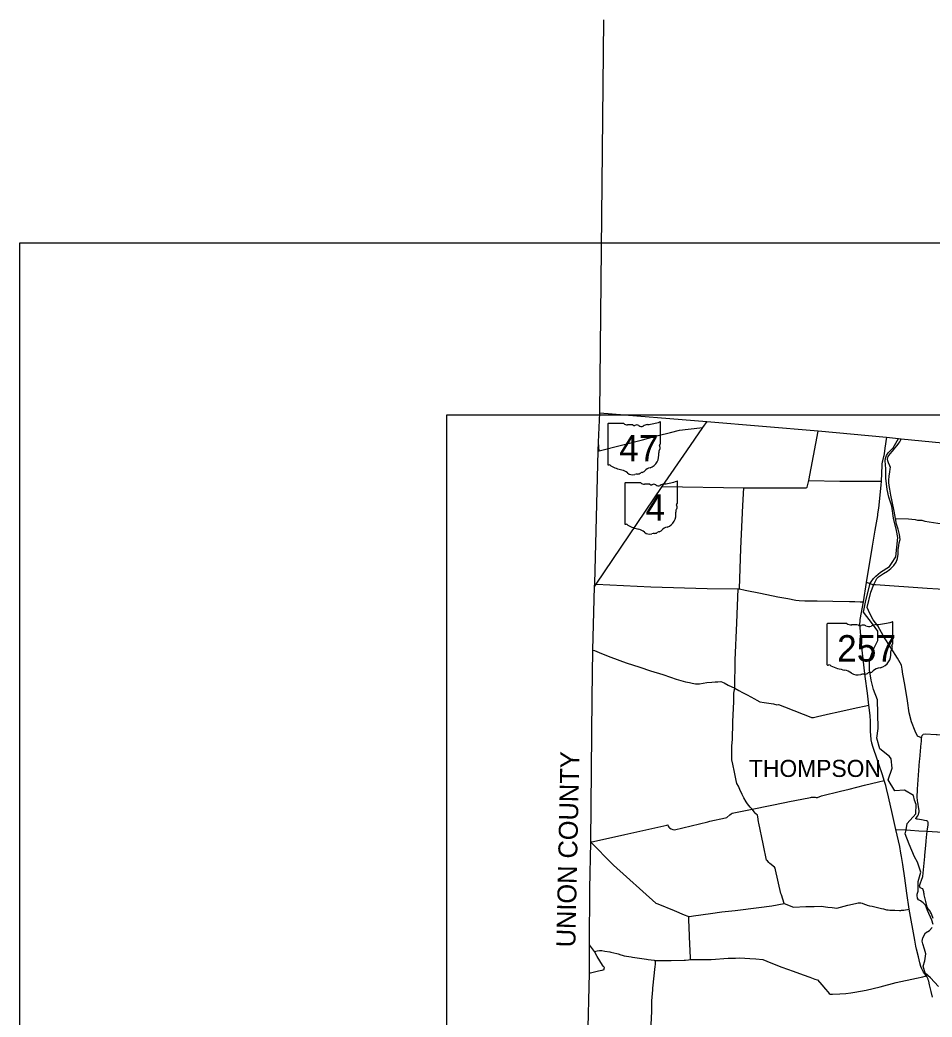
# Model space of a CAD drawing. Extents: x 1729596 to 1925846, y 659247 to 911751.
# Drawn here: x 1729596 to 1777664, y 859172 to 911751 of the extents above; entities that cross this region are included whole.
import ezdxf

# ---------------------------------------------------------------- set-up
doc = ezdxf.new("R2010")
doc.units = 0
for name, color, linetype in [('GM_X_Adjacent_County', 7, 'Continuous'), ('GM_X_Adjacent_County_Text', 7, 'Continuous'), ('GM_X_County', 7, 'Continuous'), ('GM_X_County_Road', 7, 'Continuous'), ('GM_X_State_Route', 7, 'Continuous'), ('GM_X_State_Shield', 7, 'Continuous'), ('GM_X_Township', 7, 'Continuous'), ('GM_X_Township_Road', 7, 'Continuous'), ('GM_X_Township_Text', 7, 'Continuous'), ('SC_Scratch1', 7, 'Continuous'), ('SH_Data', 7, 'Continuous')]:
    doc.layers.add(name, color=color, linetype=linetype)

msp = doc.modelspace()

# ---------------------------------------------------------------- linework, layer by layer
at = {"layer": 'GM_X_Adjacent_County'}
msp.add_line((1760161, 891042), (1760364, 911751), dxfattribs=at)
at = {"layer": 'GM_X_County'}
msp.add_lwpolyline([(1759518, 857896), (1759604, 861482), (1759615, 862978), (1759631, 865937), (1759690, 868390), (1759745, 876009), (1759795, 878524), (1759881, 881868), (1759886, 882027), (1760071, 889009), (1760084, 889480), (1760161, 891042), (1765804, 890577), (1771666, 890080), (1775269, 889747), (1775894, 889674), (1776032, 889658), (1778209, 889456)], dxfattribs=at)
at = {"layer": 'GM_X_County_Road'}
for points in [[(1759969, 881997), (1762841, 881858), (1765814, 881778), (1767451, 881759), (1767471, 881758), (1767516, 881753), (1767813, 881684), (1768617, 881522), (1769536, 881337), (1770062, 881247), (1770477, 881159), (1770666, 881130), (1770953, 881125), (1771606, 881121), (1772443, 881104), (1773313, 881088), (1773587, 881081), (1773877, 881076), (1773962, 881074), (1774048, 881064)], [(1774211, 882090), (1774252, 882089), (1774404, 882033)], [(1774404, 882033), (1774406, 882032), (1774523, 881989), (1774565, 881978), (1774598, 881976), (1774681, 881977), (1777408, 881796), (1778560, 881723), (1779427, 881668), (1779984, 881633), (1780423, 881605), (1780749, 881582)], [(1759795, 878524), (1759874, 878494), (1760252, 878350), (1760733, 878141), (1761552, 877854), (1762256, 877623), (1762819, 877435), (1763473, 877228), (1763875, 877098), (1764180, 876995), (1764428, 876912), (1764673, 876852), (1764882, 876805), (1765024, 876776), (1765203, 876738), (1765411, 876747), (1765804, 876809), (1766052, 876831), (1766236, 876847), (1766368, 876855), (1766526, 876867), (1766703, 876800), (1766927, 876678), (1767271, 876519)], [(1767271, 876519), (1767477, 876397), (1767681, 876278), (1767921, 876172), (1768111, 876051), (1768305, 875950), (1768436, 875882), (1768593, 875793), (1768820, 875758), (1769062, 875716), (1769301, 875685), (1769490, 875642), (1769580, 875657), (1769884, 875528), (1770879, 875150), (1771192, 875019), (1771304, 874972), (1771344, 874966), (1771384, 874967), (1771424, 874974), (1771622, 875018), (1772316, 875174), (1772655, 875249), (1773509, 875437), (1774333, 875620)], [(1775757, 869068), (1776296, 869048), (1776328, 869045)], [(1776328, 869045), (1776526, 869023), (1776962, 868999), (1777415, 868976), (1778218, 868930)]]:
    msp.add_lwpolyline(points, dxfattribs=at)
at = {"layer": 'GM_X_State_Route'}
for points in [[(1759881, 881868), (1759956, 881980), (1759969, 881997), (1763443, 887141), (1764744, 889038), (1765591, 890255), (1765808, 890573)], [(1760071, 889009), (1760118, 889022), (1762397, 889618), (1763225, 889831), (1763889, 890004), (1764355, 890118), (1764820, 890175), (1765591, 890255)], [(1777685, 860217), (1777620, 860525), (1777532, 860880), (1777486, 861060), (1777476, 861098), (1777464, 861135), (1777451, 861171), (1777436, 861207), (1777419, 861242), (1777383, 861311), (1777355, 861355), (1777221, 861539), (1777176, 861609), (1777119, 861721), (1777075, 861838), (1777027, 862032), (1776950, 862347), (1776840, 862758), (1776807, 862917), (1776749, 863221), (1776467, 864856), (1776332, 865707), (1776223, 866494), (1776116, 867210), (1776059, 867642), (1776027, 867820), (1775960, 868164), (1775757, 869068), (1775581, 869857), (1775376, 870780), (1775268, 871225), (1775225, 871389), (1775149, 871651), (1775057, 871948), (1774882, 872459), (1774774, 872777), (1774561, 873391), (1774496, 873614), (1774491, 873632), (1774460, 873783), (1774453, 873834), (1774417, 874231), (1774413, 874823), (1774404, 875011), (1774397, 875080), (1774333, 875620), (1774258, 876258), (1774139, 877129), (1774064, 877743), (1773968, 878674), (1773866, 879905), (1773869, 880029), (1773882, 880140), (1774048, 881064), (1774211, 882090), (1774530, 884003), (1774667, 884846), (1774801, 885624), (1774814, 885707), (1774851, 886003), (1774976, 887219), (1774992, 887423), (1775028, 888248), (1775030, 888289), (1775035, 888331), (1775040, 888372), (1775048, 888413), (1775057, 888454), (1775067, 888494), (1775128, 888732), (1775139, 888776), (1775154, 888865), (1775187, 889163), (1775276, 889757)]]:
    msp.add_lwpolyline(points, dxfattribs=at)
at = {"layer": 'GM_X_State_Shield'}
for p, q in [((1760571, 890435), (1760571, 888322)), ((1760571, 890435), (1760571, 888322)), ((1761414, 890471), (1760599, 890471)), ((1761414, 890471), (1760599, 890471)), ((1763356, 889418), (1763356, 890524)), ((1763356, 889418), (1763356, 890524)), ((1763355, 889418), (1763356, 889418)), ((1763355, 889418), (1763356, 889418)), ((1761469, 887306), (1761469, 885193)), ((1761469, 887306), (1761469, 885193)), ((1762312, 887343), (1761496, 887343)), ((1762312, 887343), (1761496, 887343)), ((1764253, 886290), (1764253, 887395)), ((1764253, 886290), (1764253, 887395)), ((1764253, 886290), (1764253, 886290)), ((1764253, 886290), (1764253, 886290)), ((1772124, 879884), (1772124, 877770)), ((1772124, 879884), (1772124, 877770)), ((1773178, 879920), (1772159, 879920)), ((1773178, 879920), (1772159, 879920)), ((1775605, 878867), (1775605, 879972)), ((1775605, 878867), (1775605, 879972)), ((1775604, 878867), (1775605, 878867)), ((1775604, 878867), (1775605, 878867))]:
    msp.add_line(p, q, dxfattribs=at)
for centre, radius, start, end in [((1760603, 890439), 32.3, 98.1301, 188.1301), ((1760603, 890439), 32.3, 98.1301, 188.1301), ((1761608, 890717), 313, 231.6195, 271.1119), ((1761608, 890717), 313, 231.6195, 271.1119), ((1761712, 889285), 1123, 80.4867, 94.9883), ((1761712, 889285), 1123, 80.4867, 94.9883), ((1761967, 890450), 90.3, 219.7921, 297.1024), ((1761967, 890450), 90.3, 219.7921, 297.1024), ((1762100, 890206), 188, 54.4667, 119.1411), ((1762100, 890206), 188, 54.4667, 119.1411), ((1762342, 890541), 226, 233.8562, 294.8282), ((1762342, 890541), 226, 233.8562, 294.8282), ((1762741, 889826), 594, 97.3462, 120.7689), ((1762741, 889826), 594, 97.3462, 120.7689), ((1762364, 893352), 2953, 275.8445, 288.9065), ((1762364, 893352), 2953, 275.8445, 288.9065), ((1763325, 890528), 31, 351.8621, 97.738), ((1763325, 890528), 31, 351.8621, 97.738), ((1763349, 889337), 48, 107.944, 210.337), ((1763349, 889337), 48, 107.944, 210.337), ((1763043, 889197), 288, 340.033, 23.6496), ((1763043, 889197), 288, 340.033, 23.6496), ((1763323, 889414), 33.2, 289.6038, 7.7341), ((1763323, 889414), 33.2, 289.6038, 7.7341), ((1762529, 888815), 739, 292.3089, 8.9858), ((1762529, 888815), 739, 292.3089, 8.9858), ((1763467, 888955), 210, 136.8065, 186.9296), ((1763467, 888955), 210, 136.8065, 186.9296), ((1760604, 888317), 32.5, 171.9584, 258.3066), ((1760604, 888317), 32.5, 171.9584, 258.3066), ((1760609, 888533), 248, 267.339, 280.6039), ((1760609, 888533), 248, 267.339, 280.6039), ((1760659, 888200), 89.5, 29.7484, 93.2717), ((1760659, 888200), 89.5, 29.7484, 93.2717), ((1761790, 890098), 2132, 240.4129, 257.1985), ((1761790, 890098), 2132, 240.4129, 257.1985), ((1762841, 887728), 404, 94.4031, 142.5768), ((1762841, 887728), 404, 94.4031, 142.5768), ((1761154, 887372), 667, 47.1842, 75.836), ((1761154, 887372), 667, 47.1842, 75.836), ((1761876, 888189), 423, 230.7004, 286.2918), ((1761876, 888189), 423, 230.7004, 286.2918), ((1762120, 887459), 348, 85.6951, 111.2099), ((1762120, 887459), 348, 85.6951, 111.2099), ((1762151, 888031), 226, 268.777, 315.5493), ((1762151, 888031), 226, 268.777, 315.5493), ((1762355, 887826), 63.5, 65.7517, 132.6484), ((1762355, 887826), 63.5, 65.7517, 132.6484), ((1762328, 888117), 239, 282.8732, 323.2771), ((1762328, 888117), 239, 282.8732, 323.2771), ((1761501, 887311), 32.3, 98.1301, 188.1301), ((1761501, 887311), 32.3, 98.1301, 188.1301), ((1762506, 887588), 313, 231.6195, 271.1119), ((1762506, 887588), 313, 231.6195, 271.1119), ((1762610, 886156), 1123, 80.4867, 94.9883), ((1762610, 886156), 1123, 80.4867, 94.9883), ((1762865, 887322), 90.3, 219.7921, 297.1024), ((1762865, 887322), 90.3, 219.7921, 297.1024), ((1762997, 887078), 188, 54.4667, 119.1411), ((1762997, 887078), 188, 54.4667, 119.1411), ((1763239, 887413), 226, 233.8562, 294.8282), ((1763239, 887413), 226, 233.8562, 294.8282), ((1763638, 886697), 594, 97.3462, 120.7689), ((1763638, 886697), 594, 97.3462, 120.7689), ((1763261, 890224), 2953, 275.8445, 288.9065), ((1763261, 890224), 2953, 275.8445, 288.9065), ((1764222, 887400), 31, 351.8621, 97.738), ((1764222, 887400), 31, 351.8621, 97.738), ((1764364, 885827), 210, 136.8065, 186.9296), ((1764364, 885827), 210, 136.8065, 186.9296), ((1764246, 886209), 48, 107.944, 210.337), ((1764246, 886209), 48, 107.944, 210.337), ((1763941, 886069), 288, 340.033, 23.6496), ((1763941, 886069), 288, 340.033, 23.6496), ((1764220, 886285), 33.2, 289.6038, 7.7341), ((1764220, 886285), 33.2, 289.6038, 7.7341), ((1763427, 885686), 739, 292.3089, 8.9858), ((1763427, 885686), 739, 292.3089, 8.9858), ((1761501, 885189), 32.5, 171.9584, 258.3066), ((1761501, 885189), 32.5, 171.9584, 258.3066), ((1761506, 885405), 248, 267.339, 280.6039), ((1761506, 885405), 248, 267.339, 280.6039), ((1761557, 885071), 89.5, 29.7484, 93.2717), ((1761557, 885071), 89.5, 29.7484, 93.2717), ((1762687, 886970), 2132, 240.4129, 257.1985), ((1762687, 886970), 2132, 240.4129, 257.1985), ((1763738, 884600), 404, 94.4031, 142.5768), ((1763738, 884600), 404, 94.4031, 142.5768), ((1762052, 884244), 667, 47.1842, 75.836), ((1762052, 884244), 667, 47.1842, 75.836), ((1762773, 885061), 423, 230.7004, 286.2918), ((1762773, 885061), 423, 230.7004, 286.2918), ((1763018, 884330), 348, 85.6951, 111.2099), ((1763018, 884330), 348, 85.6951, 111.2099), ((1763049, 884903), 226, 268.777, 315.5493), ((1763049, 884903), 226, 268.777, 315.5493), ((1763253, 884698), 63.5, 65.7517, 132.6484), ((1763253, 884698), 63.5, 65.7517, 132.6484), ((1763226, 884988), 239, 282.8732, 323.2771), ((1763226, 884988), 239, 282.8732, 323.2771)]:
    msp.add_arc(centre, radius, start, end, dxfattribs=at)
for centre, major_axis, start_param, end_param in [((1772164, 879888), (40.3, 0), 1.712693, 3.28349), ((1772164, 879888), (40.3, 0), 1.712693, 3.28349), ((1773421, 880165), (391, 0), 4.042523, 4.731795), ((1773421, 880165), (391, 0), 4.042523, 4.731795), ((1773550, 878734), (1404, 0), 1.404758, 1.657858), ((1773550, 878734), (1404, 0), 1.404758, 1.657858), ((1773869, 879899), (113, 0), 3.836095, 5.185415), ((1773869, 879899), (113, 0), 3.836095, 5.185415), ((1774035, 879655), (235, 0), 0.950623, 2.079405), ((1774035, 879655), (235, 0), 0.950623, 2.079405), ((1774337, 879990), (282, 0), 4.081561, 5.145723), ((1774337, 879990), (282, 0), 4.081561, 5.145723), ((1774836, 879275), (743, 0), 1.699011, 2.107814), ((1774836, 879275), (743, 0), 1.699011, 2.107814), ((1774365, 882801), (3691, 0), 4.814394, 5.042369), ((1774365, 882801), (3691, 0), 4.814394, 5.042369), ((1775566, 879977), (38.7, 0), 6.141152, 7.989035), ((1775566, 879977), (38.7, 0), 6.141152, 7.989035), ((1775596, 878786), (60, 0), 1.883978, 3.671073), ((1775596, 878786), (60, 0), 1.883978, 3.671073), ((1775214, 878646), (360, 0), 5.934695, 6.695948), ((1775214, 878646), (360, 0), 5.934695, 6.695948), ((1775563, 878863), (41.5, 0), 5.05454, 6.418171), ((1775563, 878863), (41.5, 0), 5.05454, 6.418171), ((1774572, 878264), (923, 0), 5.101752, 6.440018), ((1774572, 878264), (923, 0), 5.101752, 6.440018), ((1775743, 878404), (262, 0), 2.387724, 3.262537), ((1775743, 878404), (262, 0), 2.387724, 3.262537), ((1772164, 877766), (40.7, 0), 3.00124, 4.508301), ((1772164, 877766), (40.7, 0), 3.00124, 4.508301), ((1772171, 877982), (310, 0), 4.665946, 4.897461), ((1772171, 877982), (310, 0), 4.665946, 4.897461), ((1772234, 877649), (112, 0), 0.519207, 1.627899), ((1772234, 877649), (112, 0), 0.519207, 1.627899), ((1773647, 879547), (2665, 0), 4.195997, 4.488961), ((1773647, 879547), (2665, 0), 4.195997, 4.488961), ((1774961, 877177), (506, 0), 1.647645, 2.488434), ((1774961, 877177), (506, 0), 1.647645, 2.488434), ((1772853, 876821), (834, 0), 0.823519, 1.323587), ((1772853, 876821), (834, 0), 0.823519, 1.323587), ((1773755, 877638), (529, 0), 4.026481, 4.996735), ((1773755, 877638), (529, 0), 4.026481, 4.996735), ((1774060, 876907), (435, 0), 1.495662, 1.94098), ((1774060, 876907), (435, 0), 1.495662, 1.94098), ((1774099, 877480), (282, 0), 4.691044, 5.507374), ((1774099, 877480), (282, 0), 4.691044, 5.507374), ((1774354, 877275), (79.4, 0), 1.147584, 2.315152), ((1774354, 877275), (79.4, 0), 1.147584, 2.315152), ((1774320, 877566), (298, 0), 4.937069, 5.64225), ((1774320, 877566), (298, 0), 4.937069, 5.64225)]:
    msp.add_ellipse(centre, major_axis=major_axis, ratio=0.8, start_param=start_param, end_param=end_param, dxfattribs=at)
at = {"layer": 'GM_X_Township'}
for points in [[(1777723, 864054), (1777660, 864284), (1777430, 864796), (1777319, 865072), (1777194, 865201), (1777060, 865295), (1776951, 865360), (1776896, 865440), (1776878, 865579), (1776878, 865651), (1776924, 865805), (1776935, 866323), (1777068, 866814), (1776889, 867340), (1776741, 867625), (1776460, 868285), (1776256, 868836), (1776296, 869048), (1776358, 869376), (1776809, 869882), (1776827, 870373), (1776746, 870605), (1776679, 870853), (1776212, 871143), (1775698, 871106), (1775350, 871674), (1775561, 872294), (1775504, 872788), (1775414, 872915), (1774908, 873319), (1774761, 873873), (1774819, 874386), (1774803, 875172), (1774782, 875893), (1774586, 876451), (1774457, 876944), (1774369, 877473), (1774370, 877987), (1774561, 878529), (1774803, 879020), (1774811, 879521), (1774533, 879901), (1774059, 880530), (1774167, 881144), (1774406, 882032), (1774456, 882123), (1774578, 882303), (1774707, 882427), (1774948, 882624), (1775424, 882934), (1775526, 883091), (1775753, 883439), (1775862, 884465), (1775797, 884834), (1775636, 885483), (1775537, 886105), (1775391, 886594), (1775307, 886986), (1775234, 887582), (1775230, 888073), (1775193, 888494), (1775219, 888624), (1775271, 888791), (1775360, 888928), (1775618, 889192), (1775894, 889674)], [(1778010, 860785), (1777585, 861235), (1777295, 861489), (1777189, 861855), (1777288, 862139), (1777344, 862501), (1777271, 862751), (1777172, 863030), (1777146, 863168), (1777170, 863351), (1777325, 863614), (1777527, 863741), (1777673, 863892)]]:
    msp.add_lwpolyline(points, dxfattribs=at)
at = {"layer": 'GM_X_Township_Road'}
for points in [[(1763443, 887141), (1767751, 887076), (1767754, 887076), (1771026, 887079), (1771060, 887099), (1771076, 887115), (1771171, 887463), (1771666, 890061)], [(1774598, 881976), (1774720, 882234), (1774760, 882299), (1774813, 882356), (1774843, 882381), (1775103, 882554), (1775313, 882683), (1775499, 882831), (1775649, 882983), (1775766, 883156), (1775837, 883357), (1775874, 883577), (1775887, 883810), (1775907, 884030), (1775933, 884182), (1775979, 884346), (1775947, 884626), (1775885, 884907), (1775798, 885171), (1775741, 885463), (1775674, 885840), (1775571, 886351), (1775497, 886692), (1775435, 887014), (1775403, 887209), (1775389, 887360), (1775389, 887468), (1775413, 887707), (1775432, 887898), (1775464, 888072), (1775469, 888156), (1775448, 888237), (1775365, 888393), (1775328, 888495), (1775314, 888590), (1775354, 888724), (1775454, 888867), (1775584, 889017), (1775702, 889168), (1775820, 889307), (1775910, 889426), (1775960, 889506), (1776017, 889615), (1776026, 889659)], [(1760118, 889022), (1760097, 889226), (1760084, 889480)], [(1767516, 881753), (1767592, 883879), (1767693, 886154), (1767751, 887076)], [(1771171, 887463), (1772796, 887430), (1772896, 887428), (1774620, 887429), (1774992, 887423)], [(1775741, 885463), (1776426, 885437), (1776777, 885403), (1776902, 885381), (1777004, 885378), (1777125, 885372), (1777289, 885315), (1778196, 885185), (1778905, 885114), (1779153, 885103), (1779444, 885093), (1779746, 885100), (1779909, 885109), (1779987, 885117), (1780054, 885130)], [(1767271, 876519), (1767296, 877988), (1767372, 879961), (1767451, 881759)], [(1777415, 868976), (1777428, 869079), (1777461, 869308), (1777465, 869392), (1777460, 869417), (1777454, 869442), (1777439, 869470), (1777418, 869496), (1777389, 869516), (1777362, 869525), (1777107, 869568), (1776890, 869605), (1776854, 869611), (1776831, 869616), (1776818, 869633), (1776815, 869649), (1776815, 869660), (1776839, 869695), (1776908, 869790), (1776942, 869860), (1776971, 869938), (1776977, 869994), (1776978, 870056), (1776964, 870147), (1776911, 870505), (1776899, 870572), (1776883, 870783), (1776879, 870838), (1776899, 871102), (1776905, 871187), (1777011, 872662), (1777019, 872766), (1777098, 873608), (1777104, 873680), (1777108, 873786), (1777112, 873891), (1776901, 873984), (1776777, 874239), (1776590, 874743), (1776465, 875214), (1776369, 875841), (1776222, 876705), (1776122, 877260), (1776082, 877522), (1776051, 877721), (1775845, 878101), (1775513, 878619), (1775109, 879262), (1774809, 879796), (1774568, 880125), (1774383, 880446), (1774238, 880775), (1774441, 881584), (1774598, 881976)], [(1768190, 870136), (1768081, 870244), (1767947, 870409), (1767861, 870528), (1767742, 870726), (1767651, 870916), (1767543, 871171), (1767459, 871342), (1767376, 871496), (1767334, 871653), (1767253, 872089), (1767171, 872502), (1767108, 872731), (1767120, 873106), (1767121, 873461), (1767150, 873817), (1767171, 874681), (1767185, 875170), (1767198, 875395), (1767211, 875858), (1767213, 876255), (1767271, 876519)], [(1777112, 873891), (1777129, 873941), (1777152, 874011), (1777174, 874061), (1777204, 874087), (1777296, 874115), (1777876, 874078), (1777937, 874074), (1778674, 874014), (1778730, 874009), (1778734, 874009)], [(1759690, 868390), (1759727, 868410), (1761412, 868777), (1761477, 868792), (1763692, 869289), (1763746, 869301), (1763760, 869243), (1763792, 869185), (1763834, 869153), (1763918, 869091), (1763998, 869055), (1764099, 869051), (1765844, 869474), (1765945, 869498), (1766771, 869677), (1766852, 869694), (1767012, 869832), (1767086, 869895), (1767134, 869916), (1767211, 869949), (1768093, 870117), (1768190, 870136), (1770000, 870510), (1770072, 870525), (1771265, 870752), (1771318, 870762), (1771500, 870762), (1771553, 870757), (1771628, 870750), (1771831, 870839), (1772843, 871089), (1773290, 871196), (1774104, 871397), (1774834, 871578), (1775149, 871651)], [(1769863, 865161), (1769724, 865615), (1769699, 865695), (1769412, 866929), (1769391, 867020), (1769367, 867072), (1769122, 867272), (1769056, 867326), (1768985, 867405), (1768944, 867450), (1768787, 868227), (1768770, 868312), (1768540, 869397), (1768524, 869474), (1768475, 869734), (1768460, 869811), (1768385, 869886), (1768344, 869927), (1768250, 870055), (1768190, 870136)], [(1777238, 865704), (1777225, 865769), (1777214, 865830), (1777195, 865879), (1777176, 865933), (1777128, 865955), (1777042, 865995), (1777008, 866087), (1777021, 866138), (1777036, 866199), (1777129, 866446), (1777162, 866534), (1777180, 866584), (1777280, 867635), (1777287, 867710), (1777333, 868225), (1777354, 868440), (1777374, 868656), (1777389, 868796), (1777415, 868976)], [(1759690, 868390), (1760823, 867233), (1760868, 867188), (1763103, 865172), (1763217, 865148), (1764080, 864786), (1764607, 864567), (1764793, 864488), (1764809, 864483), (1764838, 864478), (1764837, 864452)], [(1777729, 864364), (1777653, 864561), (1777633, 864611), (1777585, 864705), (1777559, 864756), (1777467, 864885), (1777411, 864962), (1777339, 865271), (1777322, 865342), (1777272, 865548), (1777256, 865613), (1777242, 865686), (1777238, 865704)], [(1764838, 864478), (1764876, 864478), (1765089, 864511), (1765980, 864631), (1766593, 864719), (1767293, 864790), (1768540, 864950), (1769216, 865042), (1769863, 865161), (1770355, 864971), (1771015, 864995), (1771451, 865009), (1771818, 865018), (1772164, 864974), (1772400, 864954), (1772652, 864922), (1773233, 865070), (1773636, 865166), (1773765, 865195), (1773819, 865202), (1773867, 865200), (1773915, 865196), (1773975, 865182), (1774108, 865128), (1774162, 865106), (1774201, 865086), (1774253, 865069), (1774360, 865042), (1774506, 865023), (1775005, 864899), (1775107, 864873), (1775271, 864835), (1775313, 864827), (1775354, 864820), (1775437, 864811), (1775701, 864802), (1775944, 864798), (1776020, 864798), (1776062, 864800), (1776185, 864815), (1776467, 864856)], [(1764837, 864452), (1764833, 864303), (1764859, 863478), (1764860, 863401), (1764913, 862293), (1764917, 862205)], [(1759604, 861482), (1759656, 861496), (1759943, 861570), (1760085, 861602), (1760176, 861624), (1760279, 861650), (1760337, 861664), (1760377, 861684), (1760387, 861726), (1760397, 861779), (1760334, 861863), (1760297, 861913), (1760017, 862374), (1759867, 862636), (1759615, 862978)], [(1759867, 862636), (1760013, 862666), (1760130, 862682), (1760151, 862684), (1760179, 862685), (1760207, 862685), (1760234, 862684), (1760262, 862681), (1760414, 862652), (1760683, 862611), (1760740, 862599), (1761049, 862530), (1761122, 862513), (1761270, 862456), (1761337, 862431), (1761387, 862415), (1761439, 862399), (1761804, 862342), (1761878, 862331), (1762609, 862220), (1762700, 862206), (1763014, 862165), (1763041, 862161)], [(1764917, 862205), (1766017, 862209), (1766916, 862272), (1767304, 862272), (1767528, 862298), (1768057, 862265), (1768381, 862241), (1768751, 862199), (1769163, 862037), (1769751, 861801), (1770349, 861595), (1770876, 861403), (1771222, 861283), (1771494, 861163), (1771624, 861139), (1771860, 860864), (1772046, 860638), (1772174, 860498), (1772234, 860420), (1772290, 860376), (1772412, 860388), (1772798, 860402), (1773128, 860421), (1773381, 860443), (1773597, 860481), (1774197, 860598), (1774937, 860763), (1775772, 860991), (1776842, 861229), (1777174, 861301), (1777307, 861331), (1777355, 861355)], [(1762687, 857045), (1762714, 857325), (1762752, 857634), (1762759, 857710), (1762857, 858709), (1762863, 858776), (1762892, 859462), (1762895, 859538), (1762893, 859960), (1762893, 860024), (1762945, 860602), (1762953, 860690), (1763076, 861845), (1763087, 861944), (1763086, 862049), (1763085, 862132)], [(1763041, 862161), (1763047, 862161), (1763081, 862156), (1763820, 862158), (1763909, 862158), (1764595, 862177), (1764674, 862179), (1764832, 862196), (1764917, 862205)]]:
    msp.add_lwpolyline(points, dxfattribs=at)
at = {"layer": 'SC_Scratch1'}
msp.add_lwpolyline([(1729596, 899996), (1925846, 899996), (1925846, 765496), (1729596, 765496)], close=True, dxfattribs=at)
at = {"layer": 'SH_Data'}
for p, q in [((1752099, 890928), (1828599, 890928)), ((1752099, 814428), (1752099, 890928))]:
    msp.add_line(p, q, dxfattribs=at)

# ---------------------------------------------------------------- texts
at = {"layer": 'GM_X_Adjacent_County_Text'}
msp.add_text('UNION COUNTY', height=1000, rotation=88.7699, dxfattribs=at).set_placement((1758862, 862842))
at = {"layer": 'GM_X_State_Shield'}
for s, height, p in [('47', 1392.2, (1761177, 888471)), ('47', 1392.2, (1761177, 888471)), ('4', 1392, (1762565, 885342)), ('4', 1392, (1762565, 885342)), ('257', 1392.2, (1772660, 877919)), ('257', 1392.2, (1772660, 877919))]:
    msp.add_text(s, height=height, dxfattribs=at).set_placement(p)
at = {"layer": 'GM_X_Township_Text'}
msp.add_text('THOMPSON', height=900, rotation=0, dxfattribs=at).set_placement((1768016, 871834))

doc.saveas('drawing.dxf')
